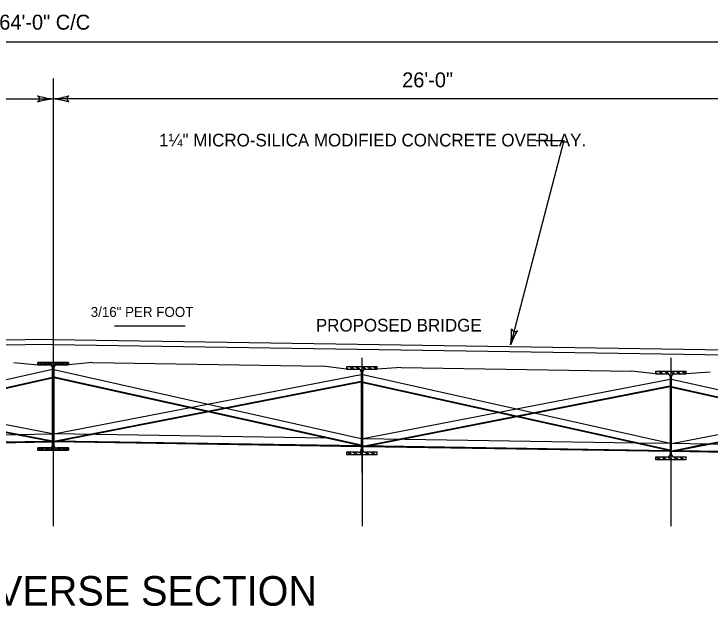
# Model space of a CAD drawing. Extents: x 10803 to 14007, y 6159 to 7440.
# Drawn here: x 13650.54 to 13672.33, y 6324.31 to 6342.86 of the extents above; entities that cross this region are included whole.
import ezdxf

# ---------------------------------------------------------------- set-up
doc = ezdxf.new("R2010")
doc.units = 0
doc.layers.add('BR_X_Slab_Object', color=7, linetype='Continuous')
doc.layers.add('Default', color=7, linetype='Continuous')

msp = doc.modelspace()

# ---------------------------------------------------------------- linework, layer by layer
at = {"layer": 'BR_X_Slab_Object'}
for p, q in [((13651.774, 6332.666), (13625.774, 6332.26)), ((13651.774, 6332.666), (13677.774, 6332.26)), ((13651.774, 6332.508), (13625.774, 6332.101)), ((13651.774, 6332.508), (13677.774, 6332.101)), ((13650.545, 6331.939), (13651.295, 6331.869)), ((13653.003, 6331.939), (13652.253, 6331.869)), ((13653.004, 6331.939), (13660.21, 6331.826)), ((13660.959, 6331.734), (13660.209, 6331.826)), ((13662.668, 6331.788), (13661.918, 6331.734)), ((13662.668, 6331.788), (13669.876, 6331.675)), ((13670.626, 6331.583), (13669.876, 6331.675)), ((13672.334, 6331.637), (13671.584, 6331.583))]:
    msp.add_line(p, q, dxfattribs=at)
at = {"layer": 'Default'}
for p, q in [((13623.264, 6341.979), (13680.285, 6341.979)), ((13651.774, 6340.832), (13651.774, 6326.816)), ((13651.286, 6340.289), (13651.285, 6340.289)), ((13652.262, 6340.289), (13652.263, 6340.289)), ((13629.264, 6340.196), (13651.774, 6340.196)), ((13674.285, 6340.196), (13651.774, 6340.196)), ((13667.756, 6338.896), (13666.091, 6332.499)), ((13666.879, 6338.896), (13667.756, 6338.896)), ((13655.903, 6333.077), (13653.698, 6333.077)), ((13666.304, 6332.948), (13666.304, 6332.948)), ((13651.774, 6332.272), (13651.774, 6328.521)), ((13651.774, 6332.272), (13651.774, 6328.521)), ((13661.438, 6332.091), (13661.438, 6328.502)), ((13671.108, 6332.091), (13671.108, 6326.816)), ((13651.295, 6331.869), (13651.295, 6331.942)), ((13651.295, 6331.942), (13652.253, 6331.942)), ((13651.295, 6331.88), (13651.357, 6331.942)), ((13652.253, 6331.942), (13651.295, 6331.942)), ((13651.295, 6331.942), (13651.295, 6331.869)), ((13651.345, 6331.869), (13651.295, 6331.919)), ((13651.667, 6331.869), (13651.295, 6331.869)), ((13651.295, 6331.869), (13651.667, 6331.869)), ((13651.341, 6331.869), (13651.414, 6331.942)), ((13651.472, 6331.869), (13651.4, 6331.942)), ((13651.529, 6331.869), (13651.456, 6331.942)), ((13651.468, 6331.869), (13651.541, 6331.942)), ((13651.524, 6331.869), (13651.597, 6331.942)), ((13651.656, 6331.869), (13651.583, 6331.942)), ((13651.798, 6331.784), (13651.64, 6331.942)), ((13651.652, 6331.869), (13651.725, 6331.942)), ((13651.667, 6331.869), (13651.667, 6331.869)), ((13651.699, 6331.86), (13651.781, 6331.942)), ((13651.75, 6331.784), (13651.908, 6331.942)), ((13651.75, 6329.348), (13651.75, 6331.786)), ((13651.75, 6331.786), (13651.75, 6329.348)), ((13651.75, 6331.727), (13651.798, 6331.775)), ((13651.798, 6331.727), (13651.75, 6331.775)), ((13651.849, 6331.86), (13651.767, 6331.942)), ((13651.798, 6331.786), (13651.798, 6329.348)), ((13651.798, 6329.348), (13651.798, 6331.786)), ((13651.897, 6331.869), (13651.824, 6331.942)), ((13652.253, 6331.869), (13651.882, 6331.869)), ((13651.882, 6331.869), (13652.253, 6331.869)), ((13651.882, 6331.869), (13651.882, 6331.869)), ((13651.892, 6331.869), (13651.965, 6331.942)), ((13652.024, 6331.869), (13651.951, 6331.942)), ((13652.081, 6331.869), (13652.008, 6331.942)), ((13652.019, 6331.869), (13652.092, 6331.942)), ((13652.076, 6331.869), (13652.149, 6331.942)), ((13652.208, 6331.869), (13652.135, 6331.942)), ((13652.253, 6331.88), (13652.191, 6331.942)), ((13652.203, 6331.869), (13652.253, 6331.919)), ((13652.253, 6331.942), (13652.253, 6331.869)), ((13652.253, 6331.869), (13652.253, 6331.942)), ((13661.918, 6331.807), (13660.959, 6331.807)), ((13660.959, 6331.807), (13660.959, 6331.734)), ((13661.009, 6331.734), (13660.959, 6331.784)), ((13661.137, 6331.734), (13661.064, 6331.807)), ((13661.193, 6331.734), (13661.12, 6331.807)), ((13661.32, 6331.734), (13661.248, 6331.807)), ((13661.463, 6331.649), (13661.304, 6331.807)), ((13661.513, 6331.725), (13661.431, 6331.807)), ((13661.561, 6331.734), (13661.488, 6331.807)), ((13661.688, 6331.734), (13661.615, 6331.807)), ((13661.745, 6331.734), (13661.672, 6331.807)), ((13661.872, 6331.734), (13661.799, 6331.807)), ((13661.918, 6331.745), (13661.856, 6331.807)), ((13661.918, 6331.734), (13661.918, 6331.807)), ((13651.753, 6331.723), (13642.134, 6329.564)), ((13651.753, 6329.713), (13642.134, 6331.568)), ((13651.75, 6331.6), (13651.798, 6331.648)), ((13651.798, 6331.6), (13651.75, 6331.648)), ((13651.75, 6331.543), (13651.798, 6331.592)), ((13651.798, 6331.543), (13651.75, 6331.592)), ((13651.796, 6331.723), (13661.414, 6329.564)), ((13651.796, 6329.713), (13661.414, 6331.568)), ((13660.959, 6331.734), (13661.331, 6331.734)), ((13661.414, 6331.651), (13661.414, 6329.213)), ((13661.463, 6331.592), (13661.414, 6331.64)), ((13661.463, 6329.213), (13661.463, 6331.651)), ((13661.463, 6331.571), (13671.081, 6329.412)), ((13661.546, 6331.734), (13661.918, 6331.734)), ((13661.546, 6331.734), (13661.546, 6331.734)), ((13671.584, 6331.656), (13670.626, 6331.656)), ((13670.626, 6331.656), (13670.626, 6331.583)), ((13670.676, 6331.583), (13670.626, 6331.633)), ((13670.626, 6331.583), (13670.998, 6331.583)), ((13670.803, 6331.583), (13670.73, 6331.656)), ((13670.86, 6331.583), (13670.787, 6331.656)), ((13670.987, 6331.583), (13670.914, 6331.656)), ((13671.129, 6331.498), (13670.971, 6331.656)), ((13671.18, 6331.574), (13671.098, 6331.656)), ((13671.228, 6331.583), (13671.155, 6331.656)), ((13671.213, 6331.583), (13671.584, 6331.583)), ((13671.213, 6331.583), (13671.213, 6331.583)), ((13671.355, 6331.583), (13671.282, 6331.656)), ((13671.411, 6331.583), (13671.339, 6331.656)), ((13671.539, 6331.583), (13671.466, 6331.656)), ((13671.584, 6331.594), (13671.522, 6331.656)), ((13671.584, 6331.583), (13671.584, 6331.656)), ((13642.13, 6329.351), (13651.748, 6331.479)), ((13642.134, 6329.33), (13651.753, 6331.458)), ((13651.753, 6329.455), (13642.134, 6331.339)), ((13651.753, 6329.476), (13642.138, 6331.359)), ((13651.75, 6331.416), (13651.798, 6331.464)), ((13651.798, 6331.416), (13651.75, 6331.464)), ((13651.75, 6331.359), (13651.798, 6331.408)), ((13651.798, 6331.359), (13651.75, 6331.408)), ((13661.414, 6329.33), (13651.796, 6331.458)), ((13651.796, 6329.476), (13661.41, 6331.359)), ((13651.796, 6329.455), (13661.414, 6331.339)), ((13661.419, 6329.351), (13651.8, 6331.479)), ((13661.463, 6331.465), (13661.414, 6331.513)), ((13661.463, 6331.408), (13661.414, 6331.457)), ((13661.463, 6329.562), (13671.081, 6331.416)), ((13671.081, 6331.5), (13671.081, 6329.062)), ((13671.129, 6331.441), (13671.081, 6331.489)), ((13671.129, 6331.314), (13671.081, 6331.362)), ((13671.128, 6331.42), (13680.747, 6329.261)), ((13671.129, 6329.062), (13671.129, 6331.5)), ((13651.75, 6331.232), (13651.798, 6331.28)), ((13651.798, 6331.232), (13651.75, 6331.28)), ((13651.75, 6331.176), (13651.798, 6331.224)), ((13651.798, 6331.176), (13651.75, 6331.224)), ((13661.463, 6331.281), (13661.414, 6331.329)), ((13661.463, 6331.224), (13661.414, 6331.273)), ((13661.463, 6331.097), (13661.414, 6331.145)), ((13671.081, 6329.179), (13661.463, 6331.307)), ((13661.463, 6329.325), (13671.077, 6331.208)), ((13661.463, 6329.304), (13671.081, 6331.188)), ((13671.085, 6329.2), (13661.467, 6331.328)), ((13671.129, 6331.257), (13671.081, 6331.306)), ((13671.129, 6331.13), (13671.081, 6331.178)), ((13671.129, 6331.073), (13671.081, 6331.122)), ((13671.128, 6329.411), (13680.747, 6331.265)), ((13680.747, 6329.028), (13671.128, 6331.156)), ((13680.751, 6329.049), (13671.133, 6331.177)), ((13651.75, 6331.048), (13651.798, 6331.097)), ((13651.798, 6331.048), (13651.75, 6331.097)), ((13651.75, 6330.992), (13651.798, 6331.04)), ((13651.798, 6330.992), (13651.75, 6331.04)), ((13651.75, 6330.864), (13651.798, 6330.913)), ((13651.798, 6330.864), (13651.75, 6330.913)), ((13661.463, 6331.041), (13661.414, 6331.089)), ((13661.463, 6330.913), (13661.414, 6330.962)), ((13661.463, 6330.857), (13661.414, 6330.905)), ((13671.129, 6330.946), (13671.081, 6330.994)), ((13671.129, 6330.889), (13671.081, 6330.938)), ((13671.128, 6329.174), (13680.743, 6331.057)), ((13671.128, 6329.153), (13680.747, 6331.037)), ((13651.75, 6330.808), (13651.798, 6330.856)), ((13651.798, 6330.808), (13651.75, 6330.856)), ((13651.75, 6330.681), (13651.798, 6330.729)), ((13651.798, 6330.681), (13651.75, 6330.729)), ((13661.463, 6330.729), (13661.414, 6330.778)), ((13661.463, 6330.673), (13661.414, 6330.721)), ((13661.441, 6330.872), (13661.441, 6326.816)), ((13671.129, 6330.762), (13671.081, 6330.811)), ((13671.129, 6330.706), (13671.081, 6330.754)), ((13651.75, 6330.624), (13651.798, 6330.672)), ((13651.798, 6330.624), (13651.75, 6330.672)), ((13651.75, 6330.497), (13651.798, 6330.545)), ((13651.798, 6330.497), (13651.75, 6330.545)), ((13651.75, 6330.44), (13651.798, 6330.489)), ((13651.798, 6330.44), (13651.75, 6330.489)), ((13661.463, 6330.546), (13661.414, 6330.594)), ((13661.463, 6330.489), (13661.414, 6330.537)), ((13671.129, 6330.578), (13671.081, 6330.627)), ((13671.129, 6330.522), (13671.081, 6330.57)), ((13651.75, 6330.313), (13651.798, 6330.361)), ((13651.798, 6330.313), (13651.75, 6330.361)), ((13651.75, 6330.256), (13651.798, 6330.305)), ((13651.798, 6330.256), (13651.75, 6330.305)), ((13661.463, 6330.362), (13661.414, 6330.41)), ((13661.463, 6330.305), (13661.414, 6330.354)), ((13671.129, 6330.395), (13671.081, 6330.443)), ((13671.129, 6330.338), (13671.081, 6330.386)), ((13671.129, 6330.211), (13671.081, 6330.259)), ((13651.75, 6330.129), (13651.798, 6330.177)), ((13651.798, 6330.129), (13651.75, 6330.177)), ((13651.75, 6330.072), (13651.798, 6330.121)), ((13651.798, 6330.072), (13651.75, 6330.121)), ((13661.463, 6330.178), (13661.414, 6330.226)), ((13661.463, 6330.121), (13661.414, 6330.17)), ((13661.463, 6329.994), (13661.414, 6330.042)), ((13671.129, 6330.154), (13671.081, 6330.202)), ((13671.129, 6330.027), (13671.081, 6330.075)), ((13651.75, 6329.945), (13651.798, 6329.994)), ((13651.798, 6329.945), (13651.75, 6329.994)), ((13651.75, 6329.889), (13651.798, 6329.937)), ((13651.798, 6329.889), (13651.75, 6329.937)), ((13661.463, 6329.937), (13661.414, 6329.986)), ((13661.463, 6329.81), (13661.414, 6329.859)), ((13671.129, 6329.97), (13671.081, 6330.019)), ((13671.129, 6329.843), (13671.081, 6329.891)), ((13671.129, 6329.786), (13671.081, 6329.835)), ((13643.22, 6329.57), (13651.753, 6329.705)), ((13651.75, 6329.761), (13651.798, 6329.81)), ((13651.798, 6329.761), (13651.75, 6329.81)), ((13651.75, 6329.705), (13651.798, 6329.753)), ((13651.798, 6329.705), (13651.75, 6329.753)), ((13651.75, 6329.578), (13651.798, 6329.626)), ((13651.798, 6329.578), (13651.75, 6329.626)), ((13660.329, 6329.57), (13651.796, 6329.705)), ((13661.463, 6329.754), (13661.414, 6329.802)), ((13661.463, 6329.626), (13661.414, 6329.675)), ((13661.463, 6329.57), (13661.414, 6329.618)), ((13671.129, 6329.659), (13671.081, 6329.707)), ((13671.129, 6329.603), (13671.081, 6329.651)), ((13642.134, 6329.33), (13651.753, 6329.481)), ((13642.138, 6329.303), (13651.753, 6329.455)), ((13651.749, 6329.336), (13651.798, 6329.385)), ((13651.75, 6329.521), (13651.798, 6329.569)), ((13651.798, 6329.521), (13651.75, 6329.569)), ((13651.75, 6329.394), (13651.798, 6329.442)), ((13651.798, 6329.394), (13651.75, 6329.442)), ((13651.8, 6329.336), (13651.75, 6329.385)), ((13661.414, 6329.33), (13651.796, 6329.481)), ((13661.411, 6329.303), (13651.796, 6329.455)), ((13661.463, 6329.443), (13661.414, 6329.491)), ((13661.463, 6329.386), (13661.414, 6329.434)), ((13669.996, 6329.419), (13661.463, 6329.554)), ((13671.081, 6329.402), (13669.995, 6329.42)), ((13671.129, 6329.475), (13671.081, 6329.524)), ((13671.129, 6329.419), (13671.081, 6329.467)), ((13679.661, 6329.268), (13671.128, 6329.403)), ((13672.172, 6329.386), (13671.129, 6329.152)), ((13651.295, 6329.192), (13651.295, 6329.272)), ((13651.295, 6329.265), (13651.667, 6329.265)), ((13651.295, 6329.25), (13651.31, 6329.265)), ((13651.667, 6329.265), (13651.295, 6329.265)), ((13651.295, 6329.265), (13651.295, 6329.192)), ((13652.253, 6329.192), (13651.295, 6329.192)), ((13651.295, 6329.192), (13652.253, 6329.192)), ((13651.392, 6329.192), (13651.319, 6329.265)), ((13651.365, 6329.192), (13651.438, 6329.265)), ((13651.448, 6329.192), (13651.375, 6329.265)), ((13651.421, 6329.192), (13651.494, 6329.265)), ((13651.576, 6329.192), (13651.503, 6329.265)), ((13651.549, 6329.192), (13651.621, 6329.265)), ((13651.632, 6329.192), (13651.559, 6329.265)), ((13651.605, 6329.192), (13651.682, 6329.269)), ((13651.759, 6329.192), (13651.684, 6329.268)), ((13651.816, 6329.192), (13651.721, 6329.287)), ((13651.732, 6329.192), (13651.828, 6329.287)), ((13651.789, 6329.192), (13651.865, 6329.268)), ((13651.943, 6329.192), (13651.867, 6329.269)), ((13651.882, 6329.265), (13652.253, 6329.265)), ((13652.253, 6329.265), (13651.882, 6329.265)), ((13651.916, 6329.192), (13651.989, 6329.265)), ((13652, 6329.192), (13651.927, 6329.265)), ((13651.973, 6329.192), (13652.046, 6329.265)), ((13652.127, 6329.192), (13652.054, 6329.265)), ((13652.1, 6329.192), (13652.173, 6329.265)), ((13652.184, 6329.192), (13652.111, 6329.265)), ((13652.157, 6329.192), (13652.23, 6329.265)), ((13652.253, 6329.25), (13652.238, 6329.265)), ((13652.253, 6329.192), (13652.253, 6329.272)), ((13652.253, 6329.265), (13652.253, 6329.192)), ((13661.463, 6329.259), (13661.414, 6329.307)), ((13661.464, 6329.201), (13661.414, 6329.25)), ((13671.081, 6329.178), (13661.463, 6329.33)), ((13671.078, 6329.152), (13661.463, 6329.304)), ((13671.129, 6329.291), (13671.081, 6329.34)), ((13671.129, 6329.235), (13671.081, 6329.283)), ((13680.747, 6329.027), (13671.128, 6329.179)), ((13661.331, 6329.13), (13660.959, 6329.13)), ((13660.959, 6329.13), (13660.959, 6329.057)), ((13660.959, 6329.057), (13661.918, 6329.057)), ((13661.056, 6329.057), (13660.983, 6329.13)), ((13661.113, 6329.057), (13661.04, 6329.13)), ((13661.24, 6329.057), (13661.167, 6329.13)), ((13661.296, 6329.057), (13661.223, 6329.13)), ((13661.424, 6329.057), (13661.348, 6329.133)), ((13661.48, 6329.057), (13661.385, 6329.152)), ((13661.608, 6329.057), (13661.531, 6329.134)), ((13661.918, 6329.13), (13661.546, 6329.13)), ((13661.664, 6329.057), (13661.591, 6329.13)), ((13661.791, 6329.057), (13661.718, 6329.13)), ((13661.848, 6329.057), (13661.775, 6329.13)), ((13661.918, 6329.115), (13661.902, 6329.13)), ((13661.918, 6329.057), (13661.918, 6329.137)), ((13670.998, 6328.979), (13670.626, 6328.979)), ((13670.626, 6328.979), (13670.626, 6328.906)), ((13670.723, 6328.906), (13670.65, 6328.979)), ((13670.779, 6328.906), (13670.706, 6328.979)), ((13670.907, 6328.906), (13670.834, 6328.979)), ((13670.963, 6328.906), (13670.89, 6328.979)), ((13671.09, 6328.906), (13671.014, 6328.982)), ((13671.147, 6328.906), (13671.052, 6329.001)), ((13671.129, 6329.108), (13671.081, 6329.156)), ((13671.131, 6329.049), (13671.081, 6329.099)), ((13680.743, 6329.001), (13671.128, 6329.153)), ((13671.274, 6328.906), (13671.198, 6328.983)), ((13671.584, 6328.979), (13671.213, 6328.979)), ((13671.331, 6328.906), (13671.258, 6328.979)), ((13671.458, 6328.906), (13671.385, 6328.979)), ((13671.515, 6328.906), (13671.442, 6328.979)), ((13671.584, 6328.964), (13671.569, 6328.979)), ((13671.584, 6328.906), (13671.584, 6328.986)), ((13670.626, 6328.906), (13671.584, 6328.906))]:
    msp.add_line(p, q, dxfattribs=at)
for centre, radius, start, end in [((13652.214, 6343.85), 3.68, 255.3829, 263.1374), ((13651.334, 6343.85), 3.68, 276.8626, 284.6171), ((13652.214, 6336.542), 3.68, 96.8626, 104.6171), ((13651.334, 6336.542), 3.68, 75.3829, 83.1374), ((13662.444, 6332.993), 3.68, 352.2739, 0.0284), ((13669.517, 6331.153), 3.68, 150.7942, 158.5486), ((13651.667, 6331.786), 0.0833, 0, 90), ((13651.667, 6331.786), 0.0833, 0, 90), ((13651.882, 6331.786), 0.0833, 90, 180), ((13651.882, 6331.786), 0.0833, 90, 180), ((13661.331, 6331.651), 0.0833, 0, 90), ((13661.546, 6331.651), 0.0833, 90, 180), ((13670.998, 6331.5), 0.0833, 0, 90), ((13671.213, 6331.5), 0.0833, 90, 180), ((13651.667, 6329.348), 0.0833, 270, 360), ((13651.667, 6329.348), 0.0833, 270, 360), ((13651.882, 6329.348), 0.0833, 180, 270), ((13651.882, 6329.348), 0.0833, 180, 270), ((13661.331, 6329.213), 0.0833, 270, 0), ((13661.546, 6329.213), 0.0833, 180, 270), ((13670.998, 6329.062), 0.0833, 270, 0), ((13671.213, 6329.062), 0.0833, 180, 270)]:
    msp.add_arc(centre, radius, start, end, dxfattribs=at)
for centre, major_axis, start_param, end_param in [((13651.221, 6340.196), (0.125, 0), 5.258637, 7.300638), ((13652.328, 6340.196), (-0.125, 0), 5.265733, 7.307734), ((13666.231, 6333.034), (-0.031, -0.121), 5.258637, 7.300638)]:
    msp.add_ellipse(centre, major_axis=major_axis, ratio=0.873734, start_param=start_param, end_param=end_param, dxfattribs=at)

# ---------------------------------------------------------------- texts
for s, height, p in [('64\'-0" C/C', 0.468, (13650.086, 6342.365)), ('26\'-0"', 0.468, (13662.696, 6340.559)), ('1¼" MICRO-SILICA MODIFIED CONCRETE OVERLAY.', 0.39687, (13655.086, 6338.708)), ('3/16" PER FOOT', 0.3125, (13652.948, 6333.369)), ('PROPOSED BRIDGE', 0.39687, (13659.996, 6332.912)), ('TRANSVERSE SECTION', 0.92604, (13645.787, 6324.328))]:
    msp.add_text(s, height=height, dxfattribs=at).set_placement(p)

doc.saveas('drawing.dxf')
